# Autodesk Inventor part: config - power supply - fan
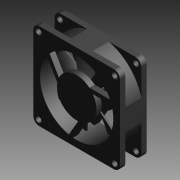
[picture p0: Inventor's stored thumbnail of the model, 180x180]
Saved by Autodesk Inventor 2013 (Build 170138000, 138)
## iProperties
Shininess: 0.0
Compacted: True
Length Units: 11269
Angle Units: 11279
Time Units: 11290
Mass Units: 11283
Length Display Precision: 3
Angle Display Precision: 2
Company: Autodesk Inc.
Created: 2000-03
Part Number: config - power supply - fan
Document SubType Name: Modeling
Designer: Autodesk Inc.
Stock Number: config - power supply - fan
Density: 1 g/cm^3
Mass: 36.3208 g
Surface Area: 214.051 cm^2
Volume: 36.3208 cm^3
Material: Allgemein
Density: 0.0
Volumn: 0.0
Area: 0.0
PropertySet Name: Model Information
Control State: 0
Checked Out: False
Master: False
Title: PC Demo
Author: Autodesk Inc.
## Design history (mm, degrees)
node "Extrusion1" dims "d1" = 20, "d2" = 0
node "Extrusion2" dims "d3" = 25, "d4" = 0
node "Hole1" dims "d9" = 4.2672, "d10" = 4, "d11" = 2, "d12" = 60 deg, "d13" = 8, "d14" = 118 deg, "d32" = 6
workaxis "Work Axis1"
workplane "Work Plane1"
node "Fillet1" dims "d21" = 4.572
node "Revolution1" dims "d20" = 90 deg
node "Extrusion3" dims "d22" = 3.9878, "d23" = 0
  sketch "Sketch5"
    geometry: C1 r 27.5 at (0, 0) reference; C2 r 14.743 at (0, 0)
    constraints: 1 centre point, 1 coincident
node "Extrusion4" dims "d24" = 3.9878, "d25" = 0
  sketch "Sketch6"
    geometry: L1 (9.497, 11.277)-(25.081, 11.277); L2 (26.201, 8.351)-(12.15, 8.351); A1 r 14.743 centre (0, 0) between (9.497, 11.277) and (12.15, 8.351) reference; A2 r 27.5 centre (0, 0) between (25.081, 11.277) and (26.201, 8.351) reference
    constraints: 4 end point, 4 point on circle, 1 horizontal, 1 parallel
node "Circular Pattern1" dims "d26" = 30, "d28" = 360 deg
workplane "Work Plane2"
node "Mirror1"
workplane "Work Plane3"
workplane "Work Plane4"
loft "Loft1" dims "d46" = 0, "d47" = 90 deg, "d48" = 0, "d49" = 90 deg
pattern_circular "Circular Pattern2" dims angle "d51" = 360 deg
revolve "Revolution2" stored, may be unused: angle "d56" = 90 deg
revolve "Revolution3" stored, may be unused: angle "d61" = 90 deg
body "Solid1"
sketch "Sketch3"
  geometry: L1 (32.5, -32.5)-(-32.5, -32.5) reference; L2 (-32.5, 32.5)-(32.5, 32.5) reference; L3 (-32.5, -32.5)-(-32.5, 32.5) reference; L4 (32.5, 32.5)-(32.5, -32.5) reference; L5 (28.5, 28.5)-(-28.5, 28.5); L6 (-28.5, 28.5)-(-28.5, -28.5); L7 (-28.5, -28.5)-(28.5, -28.5); L8 (28.5, -28.5)-(28.5, 28.5); 4 further points
  constraints: 8 end point, 4 coincident, 3 other
  dimensions: "d31" = 4 distance between parallel lines of L2 L5
sketch "Sketch7"
  geometry: L1 (2.586, 3.988)-(-14.743, 3.988) reference; L2 (2.586, 16.012)-(-14.743, 16.012) reference; L3 (0, 19.341)-(0, -3.959) reference; L4 (0, 16.012)-(0, 3.988); L5 (0, 10)-(2, 13.464); L6 (0, 10)-(-2, 6.536); A1 r 15 centre (12.471, 3.434) between (1.639, 13.81) and (-2.196, 6.578); A2 r 20 centre (16.886, -0.63) between (2.363, 13.12) and (-1.813, 6.465); A3 r 0.5 centre (2, 13.464) between (2.363, 13.12) and (1.639, 13.81); A4 r 0.2 centre (-2, 6.536) between (-2.196, 6.578) and (-1.813, 6.465); 2 further points
  constraints: 8 point on circle, 6 end point, 4 centre point, 4 point on line, 4 tangent, 2 coincident, 2 collinear, 1 midpoint
  dimensions: "d33" = 30 deg angle of L3 L5; "d34" = 4 distance of L5.start L5.end; "d35" = 15 radius of A1; "d36" = 20 radius of A2; "d37" = 0.5 radius of A3; "d38" = 0.2 radius of A4
sketch "Sketch1"
  geometry: L1 (-32.5, -32.5)-(32.5, -32.5); L2 (32.5, -32.5)-(32.5, 32.5); L3 (32.5, 32.5)-(-32.5, 32.5); L4 (-32.5, 32.5)-(-32.5, -32.5); L5 (-45.5, 0)-(45.5, 0) reference; L6 (0, 45.5)-(0, -45.5) reference
  constraints: 8 end point, 2 parallel, 1 horizontal, 1 perpendicular, 2 other
  dimensions: "d0" = 65 distance of L2.end L3.end; "d29" = 65 distance of L3.end L1.start
sketch "Sketch2"
  geometry: L1 (-32.5, -32.5)-(32.5, 32.5); C1 r 27.5 at (0, 0)
  constraints: 2 end point, 1 centre point, 1 midpoint
  dimensions: "d30" = 55 diameter of C1
sketch "Sketch4"
  geometry: L1 (33.5, -4)-(50, -4); L2 (50, -4)-(50, -16); L3 (50, -16)-(33.5, -16); L4 (33.5, -16)-(33.5, -4); L5 (32.5, -20)-(32.5, 0) reference; L6 (32.5, 0)-(-32.5, 0) reference; L7 (-32.5, -20)-(32.5, -20) reference; L8 (0, 4)-(0, -24) reference
  constraints: 8 end point, 2 parallel, 1 horizontal, 1 perpendicular
  dimensions: "d16" = 1 distance between parallel lines of L4 L5; "d17" = 16.5 distance of L2.end L3.end; "d18" = 4 distance between parallel lines of L1 L6; "d19" = 4 distance between parallel lines of L7 L3 (= d18)
sketch "Sketch8"
  geometry: L1 (0, 16.012)-(0, 3.988) reference; L2 (8.351, 16.012)-(-13.863, 16.012) reference; L3 (8.351, 3.988)-(-13.863, 3.988) reference; L4 (0, 10)-(4.83, 11.294); L5 (0, 10)-(-4.83, 8.706); A1 r 25 centre (6.871, -12.82) between (4.762, 12.091) and (-5.068, 9.145); A2 r 28 centre (6.468, -17.459) between (4.875, 10.495) and (-4.631, 8.247); A3 r 0.8 centre (4.83, 11.294) between (4.875, 10.495) and (4.762, 12.091); A4 r 0.5 centre (-4.83, 8.706) between (-5.068, 9.145) and (-4.631, 8.247)
  constraints: 8 point on circle, 4 centre point, 4 end point, 4 tangent, 2 coincident, 2 collinear, 1 midpoint
  dimensions: "d40" = 75 deg angle of L1 L4; "d41" = 5 distance of L4.start L4.end; "d42" = 0.8 radius of A3; "d43" = 0.5 radius of A4; "d44" = 25 radius of A1; "d45" = 28 radius of A2
sketch "Sketch9"
  geometry: L1 (0, 18.417)-(0, 1.583) reference; L2 (2.586, 16.012)-(-14.743, 16.012) reference; L3 (16.082, 3.988)-(2.586, 3.988) reference; L4 (0, 15.812)-(5, 15.812); L5 (5, 15.812)-(5, 4.188); L6 (5, 4.188)-(0, 4.188); L7 (0, 4.188)-(0, 15.812); 1 further point
  constraints: 8 end point, 2 parallel, 1 horizontal, 1 perpendicular, 1 point on line
  dimensions: "d53" = 0.2 distance between parallel lines of L2 L4; "d54" = 0.2 distance between parallel lines of L3 L6 (= d53); "d55" = 5 distance between parallel lines of L1 L5
sketch "Sketch10"
  geometry: L1 (-27.5, 15.812)-(-26, 15.812); L2 (-26, 15.812)-(-26, 4.188); L3 (-26, 4.188)-(-27.5, 4.188); L4 (-27.5, 4.188)-(-27.5, 15.812); L5 (0, 1.583)-(0, 18.417) reference; L6 (-5.018, 16.012)-(-14.743, 16.012) reference; L7 (-5.018, 3.988)-(-14.743, 3.988) reference; 2 further points
  constraints: 8 end point, 2 parallel, 1 horizontal, 1 perpendicular
  dimensions: "d57" = 26 distance between parallel lines of L5 L2; "d58" = 1.5 distance of L1.start L1.end; "d59" = 0.2 distance between parallel lines of L6 L1; "d60" = 0.2 distance between parallel lines of L7 L3 (= d59)
other parameters: "d15" = 90 deg, "d39" = 28
